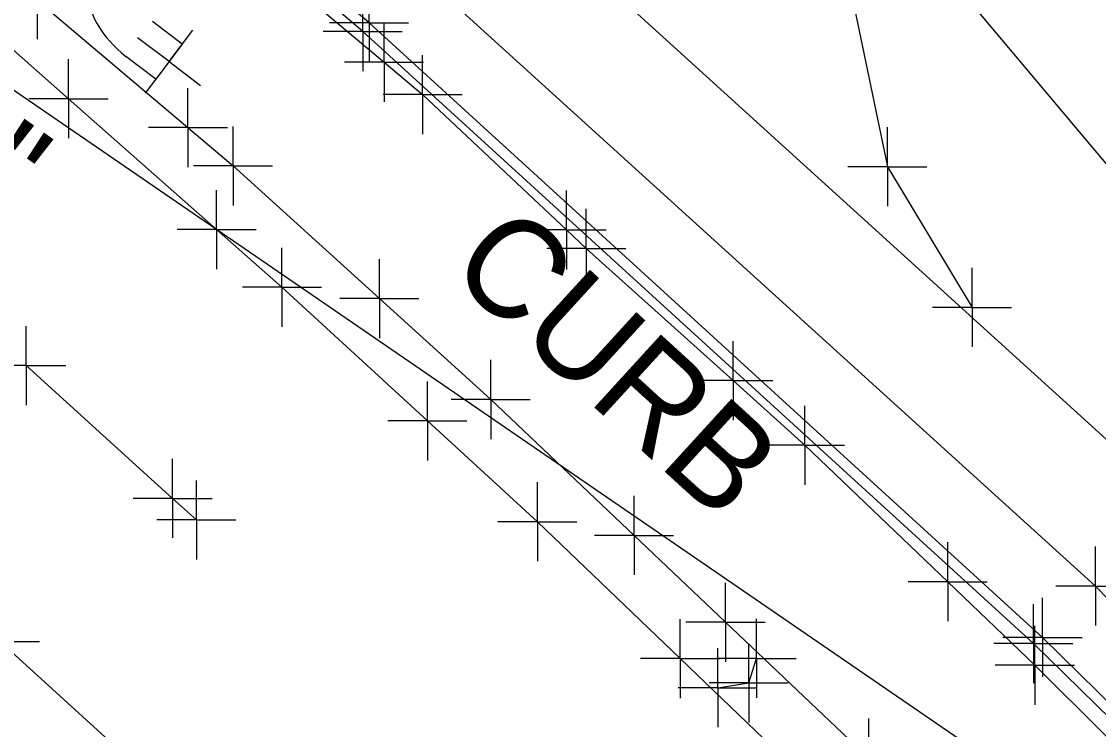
# Model space of a CAD drawing. Extents: x 0 to 1944463, y 0 to 420651.
# Drawn here: x 1942997.1 to 1943051.6, y 417692.7 to 417728.5 of the extents above; entities that cross this region are included whole.
import ezdxf

# ---------------------------------------------------------------- set-up
doc = ezdxf.new("R2010")
doc.units = 0
for name, color, linetype in [('SUR - DRG - Storm Sewer', 7, 'Continuous'), ('SUR - DRG - Storm Sewer Text', 7, 'Continuous'), ('SUR - DTM - Breaklines', 7, 'Continuous'), ('SUR - DTM - Breaklines - Points - Locators', 7, 'Continuous'), ('SUR - TR-CTRL - Pavement Marking', 7, 'Continuous'), ('SUR - TR-CTRL - Pavement Marking - Points - Locators', 7, 'Continuous'), ('SUR - TRAN - Features', 7, 'Continuous'), ('SUR - TRAN - Features - Points - Locators', 7, 'Continuous'), ('SUR - TRAN - Features Text', 7, 'Continuous'), ('SUR - VEG - Features', 7, 'Continuous')]:
    doc.layers.add(name, color=color, linetype=linetype)

msp = doc.modelspace()

# ---------------------------------------------------------------- linework, layer by layer
at = {"layer": 'SUR - DRG - Storm Sewer'}
msp.add_lwpolyline([(1942946.03, 417759.83), (1943172.9, 417604.06)], dxfattribs=at)
at = {"layer": 'SUR - DTM - Breaklines'}
for points in [[(1943051.416, 417833.759), (1943044.997, 417799.92), (1943039.654, 417768.038), (1943038.186, 417734.218), (1943040.896, 417721.157), (1943045.179, 417714.042)], [(1943113.816, 417618.747), (1943099.312, 417635.958), (1943090.009, 417648.721), (1943077.226, 417667.859), (1943069.186, 417677.24), (1943048.744, 417697.336), (1943014.67, 417728.445), (1942991.453, 417748.17), (1942972.688, 417763.041), (1942938.864, 417788.284), (1942937.547, 417790.234), (1942937.458, 417791.641), (1942938.043, 417793.096)]]:
    msp.add_lwpolyline(points, dxfattribs=at)
at = {"layer": 'SUR - DTM - Breaklines - Points - Locators'}
for p, q in [((1943014.67, 417728.445), (1943014.67, 417730.445)), ((1943014.67, 417728.445), (1943012.67, 417728.445)), ((1943014.67, 417728.445), (1943016.67, 417728.445)), ((1943014.67, 417728.445), (1943014.67, 417726.445)), ((1943040.896, 417721.157), (1943040.896, 417723.157)), ((1943040.896, 417721.157), (1943038.896, 417721.157)), ((1943040.896, 417721.157), (1943042.896, 417721.157)), ((1943040.896, 417721.157), (1943040.896, 417719.157)), ((1943045.179, 417714.042), (1943045.179, 417716.042)), ((1943045.179, 417714.042), (1943043.179, 417714.042)), ((1943045.179, 417714.042), (1943047.179, 417714.042)), ((1943045.179, 417714.042), (1943045.179, 417712.042)), ((1943048.744, 417697.336), (1943048.744, 417699.336)), ((1943048.744, 417697.336), (1943046.744, 417697.336)), ((1943048.744, 417697.336), (1943050.744, 417697.336)), ((1943048.744, 417697.336), (1943048.744, 417695.336))]:
    msp.add_line(p, q, dxfattribs=at)
at = {"layer": 'SUR - TR-CTRL - Pavement Marking'}
for p, q in [((1943005.217, 417727.365), (1943003.712, 417728.512)), ((1943005.217, 417727.365), (1943003.712, 417728.512)), ((1943005.217, 417727.365), (1943003.87, 417725.598)), ((1943005.217, 417727.365), (1943003.87, 417725.598)), ((1943003.87, 417725.598), (1943002.365, 417726.745)), ((1943003.87, 417725.598), (1943002.365, 417726.745)), ((1943004.544, 417726.482), (1943004.544, 417726.482))]:
    msp.add_line(p, q, dxfattribs=at)
for points in [[(1942888.586, 417807.457), (1942896.946, 417801.969), (1942905.305, 417796.481), (1942910.263, 417793.226), (1942918.458, 417787.496), (1942926.654, 417781.766), (1942931.271, 417778.538), (1942939.324, 417772.609), (1942947.377, 417766.681), (1942952.498, 417762.911), (1942960.396, 417756.776), (1942968.293, 417750.642), (1942969.893, 417749.399), (1942977.615, 417743.047), (1942985.338, 417736.694), (1942991.977, 417731.232), (1942999.466, 417724.605), (1943006.955, 417717.978), (1943010.255, 417715.058), (1943017.621, 417708.294), (1943023.187, 417703.184), (1943030.403, 417696.261), (1943037.62, 417689.339), (1943043.714, 417683.493)], [(1943007.774, 417732.892), (1943015.425, 417726.452), (1943017.376, 417724.81), (1943024.663, 417717.962), (1943025.661, 417717.024), (1943033.093, 417710.334), (1943036.726, 417707.064), (1943043.947, 417700.147), (1943048.356, 417695.925), (1943055.447, 417688.874), (1943059.819, 417684.526), (1943064.143, 417679.778), (1943067.842, 417675.554)], [(1942958.439, 417729.129), (1942964.173, 417724.441), (1942971.842, 417718.024), (1942976.396, 417714.213), (1942983.96, 417707.673), (1942984.57, 417707.146), (1942992.086, 417700.549), (1942995.996, 417697.117), (1943003.396, 417690.391), (1943006.377, 417687.681), (1943013.586, 417680.751), (1943014.139, 417680.22), (1943021.251, 417673.19), (1943026.036, 417668.461), (1943037.571, 417656.804)], [(1942997.318, 417711.092), (1943004.723, 417704.371), (1943005.927, 417703.278)], [(1943032.308, 417694.781), (1943033.879, 417695.028), (1943034.272, 417696.27)]]:
    msp.add_lwpolyline(points, dxfattribs=at)
msp.add_arc((1943005.732, 417731.164), 5.556, 142.6959, 232.6959, dxfattribs=at)
msp.add_arc((1943005.732, 417731.164), 5.556, 142.6959, 232.6959, dxfattribs=at)
at = {"layer": 'SUR - TR-CTRL - Pavement Marking - Points - Locators'}
for p, q in [((1943004.544, 417726.482), (1943005.756, 417728.072)), ((1943015.425, 417726.452), (1943015.425, 417728.452)), ((1943004.544, 417726.482), (1943002.953, 417727.694)), ((1942999.466, 417724.605), (1942999.466, 417726.605)), ((1943004.544, 417726.482), (1943003.332, 417724.891)), ((1943004.544, 417726.482), (1943006.135, 417725.27)), ((1943015.425, 417726.452), (1943013.425, 417726.452)), ((1943015.425, 417726.452), (1943017.425, 417726.452)), ((1943015.425, 417726.452), (1943015.425, 417724.452)), ((1943017.376, 417724.81), (1943017.376, 417726.81)), ((1943017.376, 417724.81), (1943015.376, 417724.81)), ((1943017.376, 417724.81), (1943019.376, 417724.81)), ((1943017.376, 417724.81), (1943017.376, 417722.81)), ((1942999.466, 417724.605), (1942997.466, 417724.605)), ((1942999.466, 417724.605), (1943001.466, 417724.605)), ((1942999.466, 417724.605), (1942999.466, 417722.605)), ((1943006.955, 417717.978), (1943006.955, 417719.978)), ((1943024.663, 417717.962), (1943024.663, 417719.962)), ((1943025.661, 417717.024), (1943025.661, 417719.024)), ((1943006.955, 417717.978), (1943004.955, 417717.978)), ((1943006.955, 417717.978), (1943008.955, 417717.978)), ((1943006.955, 417717.978), (1943006.955, 417715.978)), ((1943024.663, 417717.962), (1943022.663, 417717.962)), ((1943024.663, 417717.962), (1943026.663, 417717.962)), ((1943024.663, 417717.962), (1943024.663, 417715.962)), ((1943010.255, 417715.058), (1943010.255, 417717.058)), ((1943025.661, 417717.024), (1943023.661, 417717.024)), ((1943025.661, 417717.024), (1943027.661, 417717.024)), ((1943025.661, 417717.024), (1943025.661, 417715.024)), ((1943010.255, 417715.058), (1943008.255, 417715.058)), ((1943010.255, 417715.058), (1943012.255, 417715.058)), ((1943010.255, 417715.058), (1943010.255, 417713.058)), ((1942997.318, 417711.092), (1942997.318, 417713.092)), ((1943033.093, 417710.334), (1943033.093, 417712.334)), ((1942997.318, 417711.092), (1942995.318, 417711.092)), ((1942997.318, 417711.092), (1942999.318, 417711.092)), ((1942997.318, 417711.092), (1942997.318, 417709.092)), ((1943017.621, 417708.294), (1943017.621, 417710.294)), ((1943033.093, 417710.334), (1943031.093, 417710.334)), ((1943033.093, 417710.334), (1943035.093, 417710.334)), ((1943033.093, 417710.334), (1943033.093, 417708.334)), ((1943036.726, 417707.064), (1943036.726, 417709.064)), ((1943017.621, 417708.294), (1943015.621, 417708.294)), ((1943017.621, 417708.294), (1943019.621, 417708.294)), ((1943017.621, 417708.294), (1943017.621, 417706.294)), ((1943036.726, 417707.064), (1943034.726, 417707.064)), ((1943036.726, 417707.064), (1943038.726, 417707.064)), ((1943036.726, 417707.064), (1943036.726, 417705.064)), ((1943004.723, 417704.371), (1943004.723, 417706.371)), ((1943005.927, 417703.278), (1943005.927, 417705.278)), ((1943023.187, 417703.184), (1943023.187, 417705.184)), ((1943004.723, 417704.371), (1943002.723, 417704.371)), ((1943004.723, 417704.371), (1943006.723, 417704.371)), ((1943004.723, 417704.371), (1943004.723, 417702.371)), ((1943005.927, 417703.278), (1943003.927, 417703.278)), ((1943005.927, 417703.278), (1943007.927, 417703.278)), ((1943005.927, 417703.278), (1943005.927, 417701.278)), ((1943023.187, 417703.184), (1943021.187, 417703.184)), ((1943023.187, 417703.184), (1943025.187, 417703.184)), ((1943023.187, 417703.184), (1943023.187, 417701.184)), ((1943043.947, 417700.147), (1943043.947, 417702.147)), ((1943043.947, 417700.147), (1943041.947, 417700.147)), ((1943043.947, 417700.147), (1943045.947, 417700.147)), ((1943043.947, 417700.147), (1943043.947, 417698.147)), ((1943030.403, 417696.261), (1943030.403, 417698.261)), ((1943034.272, 417696.27), (1943034.272, 417698.27)), ((1943048.356, 417695.925), (1943048.356, 417697.925)), ((1942995.996, 417697.117), (1942997.996, 417697.117)), ((1943033.879, 417695.028), (1943033.879, 417697.028)), ((1943032.308, 417694.781), (1943032.308, 417696.781)), ((1943030.403, 417696.261), (1943028.403, 417696.261)), ((1943030.403, 417696.261), (1943032.403, 417696.261)), ((1943030.403, 417696.261), (1943030.403, 417694.261)), ((1943034.272, 417696.27), (1943032.272, 417696.27)), ((1943034.272, 417696.27), (1943036.272, 417696.27)), ((1943034.272, 417696.27), (1943034.272, 417694.27)), ((1943048.356, 417695.925), (1943046.356, 417695.925)), ((1943048.356, 417695.925), (1943050.356, 417695.925)), ((1943048.356, 417695.925), (1943048.356, 417693.925)), ((1943032.308, 417694.781), (1943030.308, 417694.781)), ((1943033.879, 417695.028), (1943031.879, 417695.028)), ((1943032.308, 417694.781), (1943034.308, 417694.781)), ((1943032.308, 417694.781), (1943032.308, 417692.781)), ((1943033.879, 417695.028), (1943035.879, 417695.028)), ((1943033.879, 417695.028), (1943033.879, 417693.028))]:
    msp.add_line(p, q, dxfattribs=at)
at = {"layer": 'SUR - TRAN - Features'}
for p, q in [((1942997.88, 417729.619), (1942997.88, 417727.619)), ((1943005.501, 417723.144), (1943005.501, 417725.144)), ((1943005.501, 417723.144), (1943003.501, 417723.144)), ((1943005.501, 417723.144), (1943007.501, 417723.144)), ((1943005.501, 417723.144), (1943005.501, 417721.144)), ((1943007.785, 417721.205), (1943007.785, 417723.205)), ((1943007.785, 417721.205), (1943005.785, 417721.205)), ((1943007.785, 417721.205), (1943009.785, 417721.205)), ((1943007.785, 417721.205), (1943007.785, 417719.205)), ((1943015.191, 417714.486), (1943015.191, 417716.486)), ((1943015.191, 417714.486), (1943013.191, 417714.486)), ((1943015.191, 417714.486), (1943017.191, 417714.486)), ((1943015.191, 417714.486), (1943015.191, 417712.486)), ((1943020.823, 417709.377), (1943020.823, 417711.377)), ((1943020.823, 417709.377), (1943018.823, 417709.377)), ((1943020.823, 417709.377), (1943022.823, 417709.377)), ((1943020.823, 417709.377), (1943020.823, 417707.377)), ((1943028.077, 417702.493), (1943028.077, 417704.493)), ((1943028.077, 417702.493), (1943026.077, 417702.493)), ((1943028.077, 417702.493), (1943030.077, 417702.493)), ((1943028.077, 417702.493), (1943028.077, 417700.493)), ((1943032.703, 417698.103), (1943032.703, 417700.103)), ((1943032.703, 417698.103), (1943030.703, 417698.103)), ((1943032.703, 417698.103), (1943034.703, 417698.103)), ((1943032.703, 417698.103), (1943032.703, 417696.103)), ((1943039.957, 417691.219), (1943039.957, 417693.219))]:
    msp.add_line(p, q, dxfattribs=at)
for points in [[(1943114.834, 417624.896), (1943103.453, 417639.126), (1943095.3, 417651.485), (1943083.428, 417672.654), (1943076.721, 417682.249), (1943055.252, 417704.387), (1943020.966, 417735.536), (1942996.784, 417756.051), (1942978.451, 417770.697), (1942923.479, 417810.417), (1942907.463, 417821.141), (1942884.283, 417835.758), (1942865.83, 417846.651), (1942848.31, 417856.509), (1942835.5, 417863.859), (1942826.295, 417870.821), (1942818.403, 417877.862), (1942796.294, 417899.443), (1942790.861, 417907.343), (1942782.321, 417924.544), (1942774.775, 417947.78), (1942772.79, 417958.555), (1942771.547, 417970.782), (1942773.585, 418011.209)], [(1943113.532, 417618.282), (1943099.019, 417635.522), (1943089.665, 417648.289), (1943076.796, 417667.519), (1943068.854, 417676.896), (1943048.284, 417697.021), (1943014.345, 417728.006), (1942991.136, 417747.722), (1942972.347, 417762.672), (1942938.609, 417787.801), (1942937.085, 417790.006), (1942936.962, 417791.695), (1942937.622, 417793.339)], [(1943077.317, 417667.957), (1943078.682, 417669.101), (1943071.985, 417678.84), (1943051.418, 417699.927), (1943017.221, 417730.988), (1942994.3, 417750.408), (1942974.801, 417765.977), (1942938.168, 417793.078)], [(1942997.88, 417729.619), (1943005.501, 417723.144), (1943007.785, 417721.205), (1943015.191, 417714.486), (1943020.823, 417709.377), (1943028.077, 417702.493), (1943032.703, 417698.103), (1943039.957, 417691.219), (1943045.132, 417686.308)]]:
    msp.add_lwpolyline(points, dxfattribs=at)
at = {"layer": 'SUR - TRAN - Features - Points - Locators'}
for p, q in [((1943014.345, 417728.006), (1943014.345, 417730.006)), ((1943014.345, 417728.006), (1943012.345, 417728.006)), ((1943014.345, 417728.006), (1943016.345, 417728.006)), ((1943014.345, 417728.006), (1943014.345, 417726.006)), ((1943051.418, 417699.927), (1943051.418, 417701.927)), ((1943051.418, 417699.927), (1943049.418, 417699.927)), ((1943051.418, 417699.927), (1943053.418, 417699.927)), ((1943051.418, 417699.927), (1943051.418, 417697.927)), ((1943048.284, 417697.021), (1943048.284, 417699.021)), ((1943048.284, 417697.021), (1943046.284, 417697.021)), ((1943048.284, 417697.021), (1943050.284, 417697.021)), ((1943048.284, 417697.021), (1943048.284, 417695.021))]:
    msp.add_line(p, q, dxfattribs=at)
at = {"layer": 'SUR - VEG - Features'}
msp.add_lwpolyline([(1943106.621, 417683.089), (1943098.581, 417653.35), (1943082.421, 417685.101), (1943028.095, 417749.727), (1943043.243, 417819.273), (1943053.355, 417815.961), (1943045.898, 417762.473), (1943062.652, 417728.878)], close=True, dxfattribs=at)

# ---------------------------------------------------------------- texts
at = {"layer": 'SUR - DRG - Storm Sewer Text'}
for s, height, rotation, p in [('12"', 5, 324.6404, (1942988.039, 417723.984)), ('INVERTS FROM CONST. PLANS', 4.99999, 315.739, (1942969.294, 417693.677))]:
    msp.add_text(s, height=height, rotation=rotation, dxfattribs=at).set_placement(p)
at = {"layer": 'SUR - TRAN - Features Text'}
msp.add_text('CURB', height=5, rotation=317.6043, dxfattribs=at).set_placement((1943018.528, 417715.854))

doc.saveas('drawing.dxf')
